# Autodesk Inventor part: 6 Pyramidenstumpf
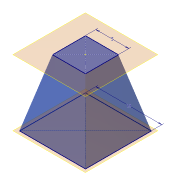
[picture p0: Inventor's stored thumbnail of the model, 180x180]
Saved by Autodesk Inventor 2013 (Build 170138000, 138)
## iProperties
Created: 2012-10
Part Number: 6 Pyramidenstumpf
Material: Allgemein
Vendor: www.inventor-faq.de
Document SubType Name: Modeling
Designer: Administrator
Manufacturer: www.inventor-faq.de
Density: 1 g/cm^3
RuleStatus: InUse
AfterDocOpen0: inventorfaq
BeforeDocSave0: inventorfaq
Author: Administrator
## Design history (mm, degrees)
sketch "Skizze1"
  geometry: L1 (-5, -5)-(5, -5); L2 (5, -5)-(5, 5); L3 (5, 5)-(-5, 5); L4 (-5, 5)-(-5, -5); L5 (-5, -5)-(5, 5); L6 (5, -5)-(-5, 5); 1 further point
  constraints: 12 end point, 2 midpoint, 2 parallel, 2 perpendicular, 1 horizontal
  dimensions: "d0" = 10 distance of L3.end L2.end
workplane "Arbeitsebene1"
sketch "Skizze3"
  geometry: L1 (-2.5, -2.5)-(2.5, -2.5); L2 (2.5, -2.5)-(2.5, 2.5); L3 (2.5, 2.5)-(-2.5, 2.5); L4 (-2.5, 2.5)-(-2.5, -2.5); L5 (-2.5, -2.5)-(2.5, 2.5); L6 (2.5, -2.5)-(-2.5, 2.5); 1 further point
  constraints: 12 end point, 2 midpoint, 2 parallel, 2 perpendicular, 1 horizontal
  dimensions: "d2" = 5 distance of L3.end L2.end
feature "Erhebung1" sketch "Skizze3" dims "d3" = 0, "d4" = 90 deg, "d5" = 0, "d6" = 90 deg
node "Volumenkörper1"
